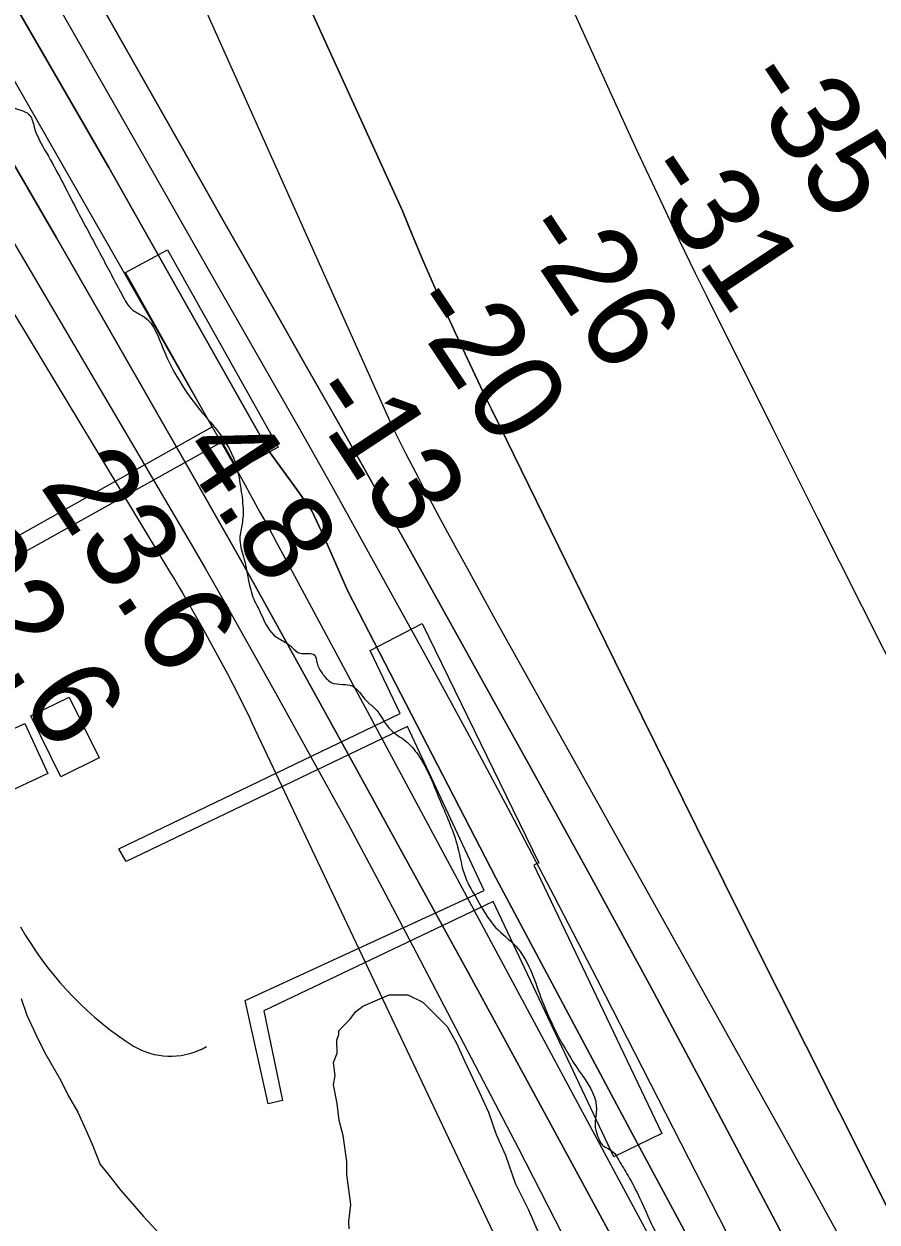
# Model space of a CAD drawing. Extents: x 3355724 to 3393621, y 594744 to 620174.
# Drawn here: x 3381547 to 3382183, y 608225 to 609116 of the extents above; entities that cross this region are included whole.
import ezdxf

# ---------------------------------------------------------------- set-up
doc = ezdxf.new("R2010")
doc.units = 0
for name, color, linetype in [('V-BLDG-OTLN', 7, 'Continuous'), ('V-CHAN-DOCK', 7, 'Continuous'), ('V-RIVR-EDGE', 7, 'Continuous'), ('V-RIVR-RANG', 7, 'Continuous'), ('V-ROAD-CNTR', 7, 'Continuous'), ('V-SITE-VEGE', 7, 'Continuous'), ('V-TOPO-DPTH', 7, 'Continuous'), ('V-TOPO-MINR', 7, 'Continuous'), ('V-TOPO-WATR', 7, 'Continuous')]:
    doc.layers.add(name, color=color, linetype=linetype)

msp = doc.modelspace()

# ---------------------------------------------------------------- linework, layer by layer
at = {"layer": 'V-BLDG-OTLN'}
for points in [[(3381574.74, 608556.21), (3381552.47, 608601.47), (3381581.12, 608615.57), (3381603.4, 608570.32)], [(3381565.18, 608558.56), (3381530.05, 608542.3), (3381528.91, 608544.76), (3381511.49, 608536.7), (3381499.09, 608563.5), (3381515.69, 608571.18), (3381511.94, 608579.27), (3381547.89, 608595.92)]]:
    msp.add_lwpolyline(points, close=True, dxfattribs=at)
at = {"layer": 'V-CHAN-DOCK'}
for points in [[(3381654.27, 608948.33), (3381736.7, 608801.46), (3381706.7, 608784.62), (3381694.93, 608805.59), (3381497.5, 608695.67), (3381489.61, 608705.79), (3381687.51, 608816.7), (3381622.89, 608931.58), (3381654.27, 608948.33)], [(3381729.15, 608312.84), (3381712.11, 608389.74), (3381890.16, 608471.66), (3381832.95, 608593.73), (3381623.35, 608493.18), (3381617.94, 608502.7), (3381827.54, 608603.26), (3381805.25, 608650.3), (3381843.95, 608670.16), (3381930.65, 608492.12), (3381927.08, 608490.32), (3382022.22, 608290.84), (3381986.49, 608273.38), (3381896.76, 608463.33), (3381725.86, 608382.04), (3381739.88, 608315.27), (3381729.15, 608312.84)]]:
    msp.add_lwpolyline(points, dxfattribs=at)
at = {"layer": 'V-RIVR-EDGE'}
msp.add_spline([(3375380.82, 618352.84), (3375420.27, 618323.73), (3375445.07, 618301.37), (3375471.34, 618279.74), (3375501.25, 618255.17), (3375536.28, 618227.67), (3375549.03, 618211.92), (3375559.98, 618204.95), (3375576.4, 618194.3), (3375599.75, 618175.24), (3375638.78, 618140.78), (3375656.28, 618122.46), (3375673.42, 618104.87), (3375771.52, 618011.41), (3375800.34, 617985.75), (3375821.85, 617963.4), (3375844.09, 617941.05), (3375861.61, 617929.67), (3375882.4, 617909.52), (3375904.26, 617880.22), (3375960.43, 617832.56), (3375992.15, 617799.58), (3376041.01, 617748.28), (3376074.55, 617712.01), (3376185.41, 617603.17), (3376226.98, 617561.76), (3376338.57, 617455.84), (3376381.97, 617411.87), (3376437.4, 617359.09), (3376479.69, 617314.75), (3376500.1, 617289.48), (3376531.46, 617257.97), (3376571.57, 617217.29), (3376620.05, 617160.14), (3376637.9, 617137.07), (3376661.24, 617115.08), (3376679.48, 617098.95), (3376697.71, 617079.53), (3376717.03, 617058.28), (3376731.6, 617036.68), (3376745.46, 617023.12), (3376758.95, 617009.2), (3376794.67, 616969.63), (3376867.2, 616883.18), (3376881.79, 616866.69), (3376901.83, 616843.98), (3376931.38, 616817.22), (3376968.56, 616773.26), (3377038.17, 616690.11), (3377066.96, 616652.75), (3377087.74, 616632.96), (3377103.06, 616618.67), (3377120.92, 616596.33), (3377186.51, 616512.45), (3377216.03, 616475.46), (3377255.39, 616427.84), (3377303.85, 616366.31), (3377369.46, 616288.29), (3377405.91, 616245.79), (3377491.52, 616128.6), (3377526.12, 616075.88), (3377552.72, 616041.09), (3377626.7, 615950.25), (3377654.4, 615916.18), (3377678.45, 615886.15), (3377699.95, 615857.22), (3377777.92, 615752.48), (3377803.06, 615722.81), (3377843.53, 615678.11), (3377867.95, 615650.27), (3377881.43, 615631.96), (3377905.48, 615598.27), (3377926.6, 615565.68), (3377940.8, 615543.35), (3377958.65, 615518.81), (3377971.76, 615499.4), (3377982.68, 615481.47), (3378059.55, 615375.27), (3378094.52, 615325.1), (3378126.94, 615277.13), (3378185.17, 615175.73), (3378207.01, 615135.1), (3378307.9, 614987.17), (3378349.41, 614923.1), (3378390.94, 614864.14), (3378419.72, 614826.42), (3378449.24, 614789.42), (3378467.07, 614756.12), (3378482.35, 614726.47), (3378509.65, 614679.24), (3378546.06, 614621.03), (3378577.36, 614566.49), (3378597.73, 614524.77), (3378622.46, 614473.89), (3378650.12, 614424.48), (3378694.9, 614351.25), (3378714.91, 614311), (3378749.11, 614248.04), (3378759.68, 614232.66), (3378776.79, 614205.93), (3378791.7, 614172.99), (3378807.69, 614137.86), (3378844.81, 614066.85), (3378863.71, 614025.13), (3378885.92, 613990.72), (3378900.11, 613964), (3378916.5, 613936.54), (3378929.25, 613918.23), (3379005.71, 613794.85), (3379023.17, 613762.64), (3379028.99, 613751.66), (3379038.1, 613737.75), (3379055.97, 613721.98), (3379063.26, 613712.46), (3379072.71, 613690.14), (3379096.69, 613633.42), (3379107.6, 613608.17), (3379127.6, 613568.28), (3379150.17, 613527.28), (3379171.28, 613493.23), (3379216.04, 613409.41), (3379256.8, 613334.37), (3379314.98, 613211.4), (3379346.24, 613141.14), (3379363.68, 613098.33), (3379415.72, 613001.69), (3379435.35, 612957.78), (3379449.52, 612923.75), (3379470.62, 612881.66), (3379540.48, 612750.98), (3379564.86, 612706.33), (3379589.61, 612660.57), (3379652.22, 612553.68), (3379662.4, 612530.99), (3379662.74, 612523.68), (3379672.94, 612508.3), (3379687.86, 612480.85), (3379704.23, 612446.81), (3379704.94, 612442.05), (3379706.03, 612437.3), (3379717.66, 612409.12), (3379731.49, 612386.43), (3379735.12, 612376.91), (3379746.04, 612354.95), (3379762.07, 612334.44), (3379789.38, 612291.97), (3379802.84, 612266.35), (3379843.96, 612191.31), (3379872.71, 612135.68), (3379896.37, 612098.33), (3379901.45, 612082.97), (3379906.5, 612054.81), (3379909.41, 612046.76), (3379918.88, 612032.84), (3379935.28, 612013.06), (3379944.73, 611991.47), (3379953.43, 611964.03), (3379958.89, 611953.42), (3379967.28, 611946.09), (3379978.56, 611926.69), (3379993.48, 611899.96), (3380009.51, 611874.34), (3380070.27, 611759.4), (3380080.8, 611731.23), (3380088.07, 611713.3), (3380095.7, 611697.56), (3380112.46, 611674.13), (3380124.83, 611651.8), (3380123.72, 611645.22), (3380124.79, 611635.35), (3380137.16, 611610.46), (3380148.81, 611592.52), (3380155.02, 611587.75), (3380167.04, 611570.54), (3380177.58, 611546.39), (3380195.78, 611514.17), (3380214.71, 611483.42), (3380224.53, 611465.85), (3380228.15, 611449.39), (3380233.59, 611432.56), (3380253.97, 611395.96), (3380276.52, 611349.11), (3380293.96, 611306.3), (3380320.89, 611258.71), (3380341.28, 611224.67), (3380352.57, 611207.46), (3380364.6, 611196.1), (3380367.14, 611187.68), (3380368.95, 611179.64), (3380378.42, 611166.45), (3380389, 611155.46), (3380388.98, 611149.98), (3380391.14, 611136.81), (3380399.14, 611120.71), (3380419.9, 611089.58), (3380436.68, 611073.46), (3380444.33, 611062.84), (3380443.95, 611058.82), (3380442.84, 611052.97), (3380446.48, 611044.92), (3380459.96, 611025.88), (3380464.31, 611010.88), (3380471.21, 610992.22), (3380486.47, 610958.19), (3380519.26, 610912.78), (3380526.88, 610891.19), (3380537.4, 610858.27), (3380551.57, 610822.77), (3380593.77, 610740.06), (3380615.24, 610699.43), (3380640.74, 610663.54), (3380652.38, 610642.31), (3380663.65, 610615.23), (3380668, 610601.33), (3380674.19, 610590.71), (3380692.06, 610574.95), (3380702.63, 610562.49), (3380712.46, 610543.83), (3380727.72, 610509.79), (3380735.35, 610487.84), (3380741.14, 610466.26), (3380745.88, 610461.13), (3380752.82, 610456.36), (3380760.47, 610445.74), (3380779.75, 610409.14), (3380795.75, 610376.2), (3380801.59, 610370.34), (3380807.42, 610366.3), (3380811.79, 610355.69), (3380812.49, 610344.36), (3380817.94, 610330.45), (3380829.23, 610313.24), (3380839.05, 610293.84), (3380846.35, 610289.44), (3380854.01, 610282.84), (3380859.1, 610273.69), (3380867.1, 610253.93), (3380868.55, 610249.54), (3380877.66, 610239.65), (3380887.13, 610223.91), (3380896.59, 610208.53), (3380899.85, 610194.27), (3380899.84, 610190.24), (3380906.05, 610188.77), (3380912.99, 610185.09), (3380918.45, 610177.04), (3380918.43, 610171.19), (3380918.42, 610164.61), (3380918.4, 610157.66), (3380926.06, 610151.8), (3380935.54, 610140.81), (3380947.18, 610118.84), (3380956.29, 610103.83), (3380965.04, 610094.67), (3380973.4, 610078.94), (3380975.21, 610070.16), (3380981.77, 610062.1), (3380992.71, 610052.93), (3380996.72, 610044.88), (3380999.97, 610032.08), (3380999.95, 610022.94), (3381003.22, 610013.06), (3381010.15, 610006.83), (3381018.91, 610001.33), (3381025.83, 609991.44), (3381035.3, 609976.79), (3381052.05, 609952.26), (3381064.06, 609932.49), (3381081.17, 609901.74), (3381081.14, 609891.87), (3381086.58, 609872.85), (3381093.84, 609850.9), (3381104.02, 609830.4), (3381125.49, 609791.6), (3381152.44, 609750.23), (3381171.02, 609723.86), (3381189.57, 609687.99), (3381212.13, 609645.9), (3381231.43, 609613.32), (3381244.14, 609581.49), (3381257.94, 609543.07), (3381275.04, 609509.4), (3381303.06, 609460.34), (3381339.81, 609389.7), (3381375.86, 609334.05), (3381398.43, 609297.8), (3381410.81, 609276.57), (3381420.3, 609271.8), (3381423.22, 609268.13), (3381426.13, 609261.55), (3381429.78, 609259.34), (3381434.89, 609258.6), (3381439.64, 609256.39), (3381499.34, 609155.72), (3381528.08, 609097.89), (3381535.35, 609085.08), (3381535.33, 609077.04), (3381535.31, 609065.34), (3381535.29, 609058.03), (3381541.13, 609053.63), (3381551.71, 609048.49), (3381554.98, 609039.7), (3381564.07, 609020.67), (3381586.27, 608978.95), (3381604.83, 608944.17), (3381620.11, 608915.26), (3381628.49, 608903.54), (3381636.88, 608898.4), (3381651.08, 608874.6), (3381663.08, 608850.81), (3381678.38, 608829.21), (3381690.77, 608814.56), (3381704.61, 608790.4), (3381708.22, 608774.67), (3381710.37, 608757.85), (3381710.35, 608748.71), (3381708.5, 608737.75), (3381708.12, 608732.26), (3381711.37, 608718), (3381715.71, 608697.15), (3381717.88, 608689.84), (3381723.34, 608678.49), (3381733.53, 608661.65), (3381741.56, 608656.51), (3381747.03, 608652.48), (3381752.87, 608648.08), (3381759.82, 608648.06), (3381763.47, 608646.95), (3381765.65, 608640.74), (3381769.29, 608633.42), (3381776.21, 608626.45), (3381784.62, 608624.97), (3381791.56, 608623.86), (3381802.13, 608612.86), (3381808.33, 608607.36), (3381820.72, 608590.88), (3381831.67, 608582.82), (3381840.78, 608572.56), (3381857.51, 608537.79), (3381870.22, 608504.13), (3381876.02, 608481.45), (3381884.75, 608464.98), (3381898.59, 608444.11), (3381913.54, 608430.18), (3381932.09, 608392.48), (3381960.83, 608337.21), (3381973.56, 608310.86), (3381973.55, 608307.21), (3381972.8, 608299.9), (3381972.79, 608295.14), (3381974.97, 608287.83), (3381977.88, 608282.34), (3381985.91, 608277.2), (3381990.28, 608270.98), (3381997.19, 608259.26), (3382005.93, 608242.42), (3382015.74, 608221.2), (3382031.03, 608193.01), (3382044.49, 608168.85), (3382063.05, 608134.08), (3382080.13, 608094.92), (3382096.49, 608059.06), (3382116.86, 608016.61), (3382135.05, 607983.3), (3382154.33, 607945.23), (3382180.52, 607889.97), (3382186.33, 607875.7), (3382201.59, 607836.91), (3382211, 607801.06), (3382218.99, 607778.02), (3382226.27, 607767.03), (3382233.56, 607756.78), (3382247.73, 607722.75), (3382259, 607698.23), (3382261.54, 607688.35), (3382266.62, 607674.81), (3382271, 607670.42), (3382277.91, 607659.43), (3382286.29, 607646.25), (3382288.82, 607636.74), (3382293.54, 607621.01), (3382300.43, 607600.89), (3382310.61, 607578.93), (3382319.72, 607565.75), (3382337.93, 607536.82), (3382350.3, 607516.32), (3382357.57, 607499.12), (3382366.3, 607481.92), (3382374.32, 607469.47), (3382380.88, 607463.97), (3382386.73, 607463.23), (3382390.75, 607463.22), (3382394.4, 607459.92), (3382404.95, 607439.06), (3382412.58, 607420.03), (3382419.09, 607395.52), (3382431.81, 607365.52), (3382444.54, 607336.97), (3382461.28, 607305.86), (3382481.64, 607263.77), (3382528.25, 607190.18), (3382546.82, 607161.62), (3382558.1, 607140.03), (3382565.37, 607121.36), (3382577.74, 607099.04), (3382593.75, 607069.75), (3382609.41, 607044.12), (3382624.34, 607021.42), (3382632.36, 607011.17), (3382645.48, 606997.98), (3382659.35, 606986.98), (3382671.37, 606972.69), (3382685.21, 606951.82)], degree=3, dxfattribs=at)
at = {"layer": 'V-ROAD-CNTR'}
msp.add_lwpolyline([(3381544.88, 608444.47), (3381548.54, 608438.2), (3381552.39, 608432.04), (3381556.4, 608425.99), (3381560.59, 608420.06), (3381564.95, 608414.25), (3381569.47, 608408.57), (3381574.15, 608403.02), (3381578.99, 608397.61), (3381583.98, 608392.33), (3381589.12, 608387.21), (3381594.41, 608382.23), (3381599.83, 608377.41), (3381605.4, 608372.74), (3381611.09, 608368.24), (3381616.91, 608363.9), (3381622.85, 608359.73), (3381628.91, 608355.73), (3381631.84, 608354.12), (3381634.87, 608352.69), (3381637.98, 608351.45), (3381641.17, 608350.41), (3381644.41, 608349.57), (3381647.7, 608348.93), (3381651.02, 608348.49), (3381654.36, 608348.26), (3381657.71, 608348.23), (3381661.05, 608348.42), (3381664.38, 608348.81), (3381667.67, 608349.4), (3381670.92, 608350.2), (3381674.12, 608351.2), (3381677.25, 608352.4), (3381680.3, 608353.78), (3381683.25, 608355.35)], dxfattribs=at)
at = {"layer": 'V-SITE-VEGE'}
for points in [[(3381545.26, 608391.25), (3381549.49, 608378.75), (3381557.91, 608360.7), (3381563.52, 608349.6), (3381574.73, 608330.18), (3381580.35, 608319.07), (3381587.35, 608306.59), (3381594.37, 608291.32), (3381598.59, 608281.6), (3381604.21, 608267.72), (3381609.81, 608260.79), (3381619.59, 608248.31), (3381626.58, 608240), (3381636.37, 608228.91), (3381651.74, 608212.29)], [(3381789.4, 608219.84), (3381789.38, 608225.4), (3381790.71, 608237.93), (3381789.27, 608249.05), (3381787.84, 608260.17), (3381787.79, 608269.9), (3381784.93, 608289.36), (3381782.1, 608300.48), (3381780.65, 608312.99), (3381777.81, 608326.88), (3381779.17, 608333.84), (3381777.74, 608343.57), (3381780.49, 608350.54), (3381780.45, 608360.28), (3381781.82, 608364.45), (3381781.81, 608367.24), (3381784.58, 608370.03), (3381790.12, 608375.62), (3381794.27, 608381.2), (3381799.81, 608385.4), (3381812.31, 608391.01), (3381819.25, 608393.82), (3381833.16, 608393.89), (3381844.31, 608388.37), (3381855.48, 608377.29), (3381862.46, 608370.37), (3381869.48, 608357.88), (3381875.09, 608345.39), (3381886.32, 608321.79), (3381893.34, 608306.52), (3381898.98, 608289.86), (3381906, 608274.59), (3381913.04, 608253.75), (3381922.86, 608234.33), (3381929.89, 608217.67)]]:
    msp.add_lwpolyline(points, dxfattribs=at)
at = {"layer": 'V-TOPO-DPTH'}
for points in [[(3381037.48, 610024.29), (3381073.93, 609958.64), (3381140.04, 609836.72), (3381236.67, 609665.35), (3381370.61, 609428.33), (3381378.24, 609413.83), (3381385.86, 609399.34), (3381397.73, 609377.18), (3381610.52, 609009.69), (3381730.05, 608798.24), (3381750.42, 608770.1), (3381761.45, 608754.74), (3381770.76, 608735.14), (3381788.54, 608694.23), (3381898.7, 608481.1), (3381998.7, 608293.54), (3382137.69, 608035.22)], [(3381037.48, 610024.29), (3381073.93, 609958.64), (3381140.04, 609836.72), (3381236.67, 609665.35), (3381370.61, 609428.33), (3381378.24, 609413.83), (3381385.86, 609399.34), (3381397.73, 609377.18), (3381610.52, 609009.69), (3381730.05, 608798.24), (3381750.42, 608770.1), (3381761.45, 608754.74), (3381770.76, 608735.14), (3381788.54, 608694.23), (3381898.7, 608481.1), (3381998.7, 608293.54), (3382137.69, 608035.22)], [(3381581.5, 609520.3), (3381829.14, 608977.38), (3381836.76, 608959.02), (3381844.47, 608940.71), (3381852.35, 608922.47), (3381860.47, 608904.33), (3381868.75, 608886.26), (3381879.35, 608863.55), (3381883.32, 608855.09), (3381887.33, 608846.65), (3381891.37, 608838.23), (3381895.46, 608829.83), (3381967.43, 608682.63), (3382007.67, 608600.71), (3382048.1, 608518.88), (3382088.82, 608437.2), (3382129.74, 608355.62), (3382254.29, 608108.42)], [(3382254.29, 608108.42), (3382129.74, 608355.62), (3382088.82, 608437.2), (3382048.1, 608518.88), (3382007.67, 608600.71), (3381967.43, 608682.63), (3381895.46, 608829.83), (3381891.37, 608838.23), (3381887.33, 608846.65), (3381883.32, 608855.09), (3381879.35, 608863.55), (3381868.75, 608886.26), (3381860.47, 608904.33), (3381852.35, 608922.47), (3381844.47, 608940.71), (3381836.76, 608959.02), (3381829.14, 608977.38), (3381581.5, 609520.3)], [(3382182.1, 608081.78), (3382104.73, 608229.35), (3382059.85, 608314.21), (3382014.56, 608398.85), (3381968.66, 608483.15), (3381922.34, 608567.24), (3381836.38, 608721.98), (3381817.87, 608755.17), (3381799.28, 608788.31), (3381780.58, 608821.38), (3381761.8, 608854.42), (3381757.85, 608861.33), (3381737.05, 608897.79), (3381716.27, 608934.27), (3381695.51, 608970.75), (3381674.77, 609007.25), (3381433.11, 609432.85)], [(3382182.1, 608081.78), (3382104.73, 608229.35), (3382059.85, 608314.21), (3382014.56, 608398.85), (3381968.66, 608483.15), (3381922.34, 608567.24), (3381836.38, 608721.98), (3381817.87, 608755.17), (3381799.28, 608788.31), (3381780.58, 608821.38), (3381761.8, 608854.42), (3381757.85, 608861.33), (3381737.05, 608897.79), (3381716.27, 608934.27), (3381695.51, 608970.75), (3381674.77, 609007.25), (3381433.11, 609432.85)], [(3382096.16, 608009.28), (3381963.35, 608254), (3381920.51, 608332.74), (3381877.56, 608411.42), (3381834.45, 608490.02), (3381791.24, 608568.55), (3381734.69, 608671.06), (3381719.6, 608698.26), (3381704.42, 608725.41), (3381689.1, 608752.49), (3381673.7, 608779.51), (3381638.17, 608841.47), (3381604.88, 608899.41), (3381571.52, 608957.31), (3381538.05, 609015.14), (3381504.51, 609072.93), (3381345.67, 609346.01)], [(3381952.91, 609134.53), (3381969.65, 609096.86), (3381986.74, 609059.34), (3382004.05, 609021.93), (3382023.51, 608980.38), (3382031.32, 608963.85), (3382039.23, 608947.35), (3382047.26, 608930.91), (3382055.37, 608914.52), (3382105, 608815.14), (3382138.06, 608749.13), (3382171.23, 608683.16), (3382204.56, 608617.28), (3382237.98, 608551.45), (3382348.57, 608334.28), (3382354.82, 608321.86), (3382360.98, 608309.39), (3382367, 608296.87), (3382372.95, 608284.3), (3382378.7, 608271.64), (3382384.29, 608258.92), (3382389.64, 608246.09), (3382394.82, 608233.2), (3382398.89, 608222.78)], [(3381952.91, 609134.53), (3381969.65, 609096.86), (3381986.74, 609059.34), (3382004.05, 609021.93), (3382023.51, 608980.38), (3382031.32, 608963.85), (3382039.23, 608947.35), (3382047.26, 608930.91), (3382055.37, 608914.52), (3382105, 608815.14), (3382138.06, 608749.13), (3382171.23, 608683.16), (3382204.56, 608617.28), (3382237.98, 608551.45), (3382348.57, 608334.28), (3382354.82, 608321.86), (3382360.98, 608309.39), (3382367, 608296.87), (3382372.95, 608284.3), (3382378.7, 608271.64), (3382384.29, 608258.92), (3382389.64, 608246.09), (3382394.82, 608233.2), (3382398.89, 608222.78)]]:
    msp.add_lwpolyline(points, dxfattribs=at)
at = {"layer": 'V-TOPO-MINR'}
for points in [[(3380902.1, 609969.88), (3381273.88, 609341.84), (3381274.86, 609340.19), (3381276.83, 609336.9), (3381277.81, 609335.25), (3381279.78, 609331.97), (3381280.77, 609330.33), (3381281.76, 609328.68), (3381656.54, 608707.85), (3381659.58, 608702.77), (3381662.6, 608697.67), (3381665.58, 608692.55), (3381668.53, 608687.42), (3381681.06, 608665.45), (3381690.08, 608649.23), (3381698.86, 608632.89), (3381707.29, 608616.36), (3381715.49, 608599.71), (3381717.04, 608596.47), (3382016.57, 607963.95)], [(3381081.16, 609889.43), (3381342.49, 609420.09), (3381344.45, 609416.56), (3381346.41, 609413.04), (3381348.37, 609409.51), (3381350.33, 609405.98), (3381353.37, 609400.48), (3381353.81, 609399.7), (3381356.14, 609395.56), (3381356.27, 609395.32), (3381691.49, 608809.67), (3381697.89, 608798.43), (3381704.26, 608787.17), (3381710.58, 608775.89), (3381716.87, 608764.58), (3381723.11, 608753.26), (3381729.32, 608741.91), (3381735.49, 608730.54), (3381741.64, 608719.16), (3381886.02, 608450.28), (3381925.47, 608376.85), (3381964.92, 608303.42), (3382004.39, 608230), (3382043.87, 608156.59)], [(3381134.81, 609644.4), (3381267.7, 609415.27), (3381284.66, 609386.11), (3381301.67, 609356.97), (3381318.75, 609327.88), (3381335.87, 609298.82), (3381366.17, 609247.56), (3381398.47, 609192.88), (3381430.76, 609138.2), (3381463.03, 609083.51), (3381495.3, 609028.81), (3381664.48, 608741.92), (3381673.54, 608726.43), (3381682.55, 608710.9), (3381691.46, 608695.32), (3381700.31, 608679.71), (3381735.93, 608616.36), (3381762.32, 608568.93), (3381788.42, 608521.33), (3381814.06, 608473.49), (3381839.41, 608425.49), (3381915.63, 608279.48), (3381932.09, 608247.6), (3381948.36, 608215.61)], [(3381581.5, 609520.3), (3381829.14, 608977.38), (3381836.76, 608959.02), (3381844.47, 608940.71), (3381852.35, 608922.47), (3381860.47, 608904.33), (3381868.75, 608886.26), (3381879.35, 608863.55), (3381883.32, 608855.09), (3381887.33, 608846.65), (3381891.37, 608838.23), (3381895.46, 608829.83), (3381967.43, 608682.63), (3382007.67, 608600.71), (3382048.1, 608518.88), (3382088.82, 608437.2), (3382129.74, 608355.62), (3382254.29, 608108.42)], [(3381518.59, 609491.97), (3381821.94, 608815.97), (3381826.73, 608806.48), (3381831.55, 608797.01), (3381836.39, 608787.55), (3381841.28, 608778.12), (3381846.21, 608768.71), (3381851.21, 608759.33), (3381856.25, 608749.98), (3381866.86, 608730.43), (3381877.28, 608711.34), (3381887.74, 608692.28), (3381898.27, 608673.26), (3381908.85, 608654.26), (3382084.78, 608339.61), (3382108.64, 608296.83), (3382132.44, 608254.01), (3382156.15, 608211.14)], [(3381433.11, 609432.85), (3381674.77, 609007.25), (3381695.51, 608970.75), (3381716.27, 608934.27), (3381737.05, 608897.79), (3381757.85, 608861.33), (3381761.8, 608854.42), (3381780.58, 608821.38), (3381799.28, 608788.31), (3381817.87, 608755.17), (3381836.38, 608721.98), (3381922.34, 608567.24), (3381968.66, 608483.15), (3382014.56, 608398.85), (3382059.85, 608314.21), (3382104.73, 608229.35), (3382182.1, 608081.78)], [(3381345.67, 609346.01), (3381504.51, 609072.93), (3381538.05, 609015.14), (3381571.52, 608957.31), (3381604.88, 608899.41), (3381638.17, 608841.47), (3381673.7, 608779.51), (3381689.1, 608752.49), (3381704.42, 608725.41), (3381719.6, 608698.26), (3381734.69, 608671.06), (3381791.24, 608568.55), (3381834.45, 608490.02), (3381877.56, 608411.42), (3381920.51, 608332.74), (3381963.35, 608254), (3382096.16, 608009.28)], [(3381551.81, 609166.85), (3381596.62, 609088.05), (3381641.52, 609009.29), (3381686.47, 608930.56), (3381752.45, 608815.14), (3381764.4, 608794.12), (3381776.29, 608773.06), (3381788.08, 608751.94), (3381799.81, 608730.79), (3381843.57, 608651.41), (3381876.84, 608590.38), (3381909.72, 608529.15), (3381942.03, 608467.61), (3381973.95, 608405.87), (3382070.4, 608217.14)], [(3381952.91, 609134.53), (3381969.65, 609096.86), (3381986.74, 609059.34), (3382004.05, 609021.93), (3382023.51, 608980.38), (3382031.32, 608963.85), (3382039.23, 608947.35), (3382047.26, 608930.91), (3382055.37, 608914.52), (3382105, 608815.14), (3382138.06, 608749.13), (3382171.23, 608683.16), (3382204.56, 608617.28), (3382237.98, 608551.45), (3382348.57, 608334.28), (3382354.82, 608321.86), (3382360.98, 608309.39), (3382367, 608296.87), (3382372.95, 608284.3), (3382378.7, 608271.64), (3382384.29, 608258.92), (3382389.64, 608246.09), (3382394.82, 608233.2), (3382398.89, 608222.78)]]:
    msp.add_lwpolyline(points, dxfattribs=at)
at = {"layer": 'V-TOPO-WATR'}
msp.add_lwpolyline([(3382137.69, 608035.22), (3381998.7, 608293.54), (3381898.7, 608481.1), (3381788.54, 608694.23), (3381770.76, 608735.14), (3381761.45, 608754.74), (3381750.42, 608770.1), (3381730.05, 608798.24), (3381610.52, 609009.69), (3381397.73, 609377.18), (3381385.86, 609399.34), (3381378.24, 609413.83), (3381370.61, 609428.33), (3381236.67, 609665.35), (3381140.04, 609836.72), (3381073.93, 609958.64), (3381037.48, 610024.29)], dxfattribs=at)

# ---------------------------------------------------------------- texts
at = {"layer": 'V-RIVR-RANG'}
for s, rotation, p in [('-35', 303.68808, (3382078.6, 609073.72)), ('-31', 303.68808, (3382003.89, 609005.51)), ('-26', 303.68808, (3381913.08, 608961.44)), ('-20', 303.68808, (3381829.3, 608906.84)), ('-13', 303.40833, (3381754.19, 608839.83)), ('4.8', 303.40833, (3381661.11, 608799.32)), ('23.6', 303.40833, (3381558.45, 608773.34)), ('22.6', 303.40833, (3381475.11, 608718.08))]:
    msp.add_text(s, height=67, rotation=rotation, dxfattribs=at).set_placement(p)

doc.saveas('drawing.dxf')
